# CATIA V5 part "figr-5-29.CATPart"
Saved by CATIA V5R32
Part number: Part1
Bounding box of the stored display mesh (mm): x -100 to 100, y -100 to 100, z 0 to 57
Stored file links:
  D:\PROJECTS\Project 2022\CATIA V5 6R 2022\Resources\Part Files\c05_catia_v5_6r2022_prt\figr-5-29.CATPart
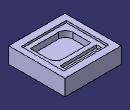
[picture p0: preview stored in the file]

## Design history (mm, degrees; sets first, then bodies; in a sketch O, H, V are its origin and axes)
Body1 (main body)
  Sketch1 on xy-plane, origin (0, 0, 0), H (1, 0, 0), V (0, 1, 0)
    line L1 (-100, 100) -> (100, 100)
    line L2 (100, 100) -> (100, -100)
    line L3 (100, -100) -> (-100, -100)
    line L4 (-100, -100) -> (-100, 100)
    axis line L5 (100, -100) -> (-100, 100)
    length L3 = 200
    length L2 = 200
    horizontal: L1 H, L3 H
    vertical: L2 V, L4 V
    midpoint: L5 O
  Pad1: profile Sketch1, direction (0, 0, 1), length 57
  Sketch2 on face of Pad1, origin (0, 0, 57), H (1, 0, 0), V (0, 1, 0)
    line L1 (-80.0557, 75.5465) -> (80.0557, 75.5465)
    line L2 (80.0557, 75.5465) -> (80.0557, -75.5465)
    line L3 (80.0557, -75.5465) -> (-80.0557, -75.5465)
    line L4 (-80.0557, -75.5465) -> (-80.0557, 75.5465)
    axis line L5 (80.0557, -75.5465) -> (-80.0557, 75.5465)
    line L6 (-62.1297, 30.1268) -> (-62.1297, -34.9955)
    arc A1 centre (-37.2362, -34.9955) radius 24.8935 from (-62.1297, -34.9955) to (-37.2362, -59.889) ccw
    line L7 (-37.2362, -59.889) -> (63.4636, -59.889)
    point P9 (63.4636, -59.889)
    line L8 (63.4636, -59.889) -> (63.4636, 3.0218)
    arc A2 centre (36.331, 3.0218) radius 27.1326 from (63.4636, 3.0218) to (35.1072, 30.1268) ccw
    line L9 (35.1072, 30.1268) -> (-62.1297, 30.1268)
    point P13 (-66.3387, 62.6022)
    line L10 (-66.3387, 62.6022) -> (63.4636, 62.6022)
    line L11 (63.4636, 62.6022) -> (63.4636, 45.9932)
    line L12 (63.4636, 45.9932) -> (-66.3387, 45.9932)
    line L13 (-66.3387, 45.9932) -> (-66.3387, 62.6022)
    point P15 (63.4636, 45.9932)
    horizontal: L1 H, L3 H, L9 H, L10 H, L12 H
    vertical: L2 V, L4 V, L6 V, L8 V, L11 V, L13 V
    midpoint: O L5
    tangency: A1 L6, L7 A1, A2 L5, A2 L8
    coincidence: P9 L5, P13 L5, P15 L8
  MultiPocket1: profile Sketch2, domains (length 17; length 28; length 7)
